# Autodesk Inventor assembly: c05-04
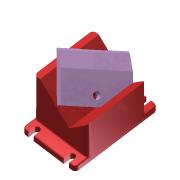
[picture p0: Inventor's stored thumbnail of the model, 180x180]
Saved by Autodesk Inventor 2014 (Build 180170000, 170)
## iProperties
Created: 2010-11
Part Number: c05-04
Document SubType Name: Assembly
Designer: Thom Tremblay
Author: Thom Tremblay
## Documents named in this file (3)
- C:\Inventor 2014 Essentials\Assemblies\Chapter 05\c05-04.iam
- C:\Inventor 2014 Essentials\Parts\Chapter 05\c05-03.ipt
- C:\Inventor 2014 Essentials\Parts\Chapter 05\c05-04.ipt
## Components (2 placed, 2 different names)
1. c05-03:1 — Insert:1
2. c05-04:1 — Insert:1
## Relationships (1: Insert 1)
- Insert:1: c05-03:1 ↔ c05-04:1
